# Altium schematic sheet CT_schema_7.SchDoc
size 302 x 170 mm
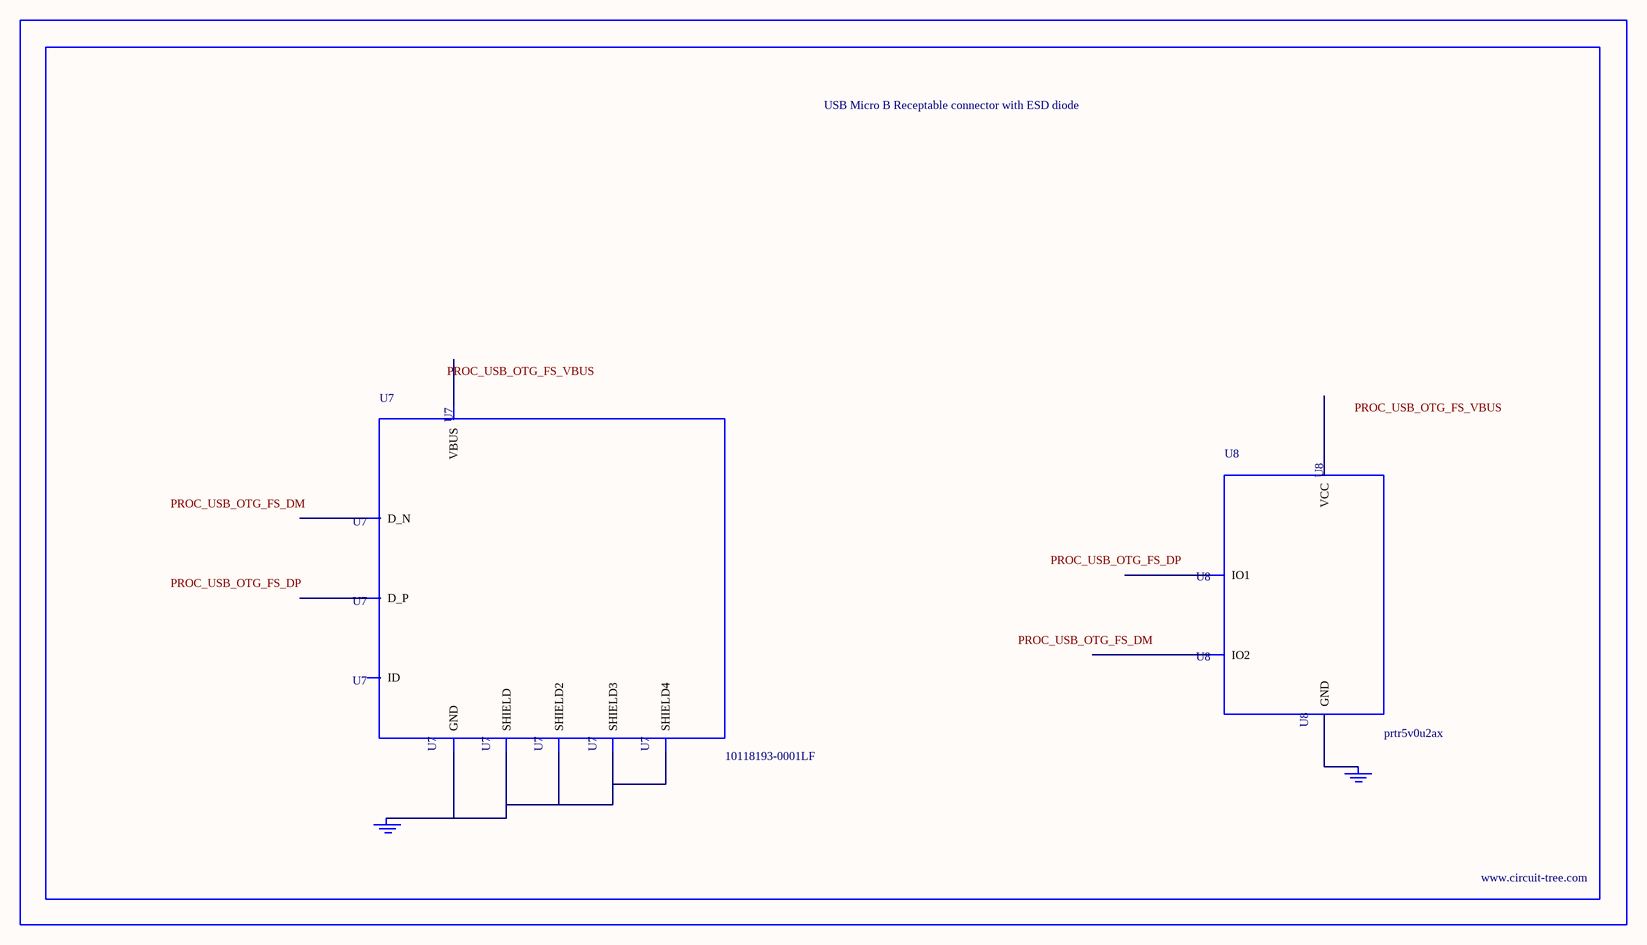
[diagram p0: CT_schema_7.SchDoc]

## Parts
BORDER6  (no value)
GND_INSTANCE_6_0  (no value)
GND_INSTANCE_6_1  (no value)
U7  10118193-0001LF  [FCI_10118193-0001LF]
U8  prtr5v0u2ax  [SOT143B]

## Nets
NetGND_INSTANCE_6_0_0: GND_INSTANCE_6_0.0(GND) U7.5(GND) U7.6(SHIELD) U7.7(SHIELD2) U7.8(SHIELD3) U7.9(SHIELD4)
NetGND_INSTANCE_6_1_0: GND_INSTANCE_6_1.0(GND) U8.1(GND)

Not connected (* = marked no-connect by the designer): U7 1(VBUS) 2(D_N) 3(D_P) 4(ID); U8 2(IO1) 3(IO2) 4(VCC)

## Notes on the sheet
- Labels drawn without touching a wire or pin: PROC_USB_OTG_FS_DM, PROC_USB_OTG_FS_DP, PROC_USB_OTG_FS_VBUS

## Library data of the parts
BORDER6 = BORDER_PAGE6
GND_INSTANCE_6_0 GND_INSTANCE_6_1 = GND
